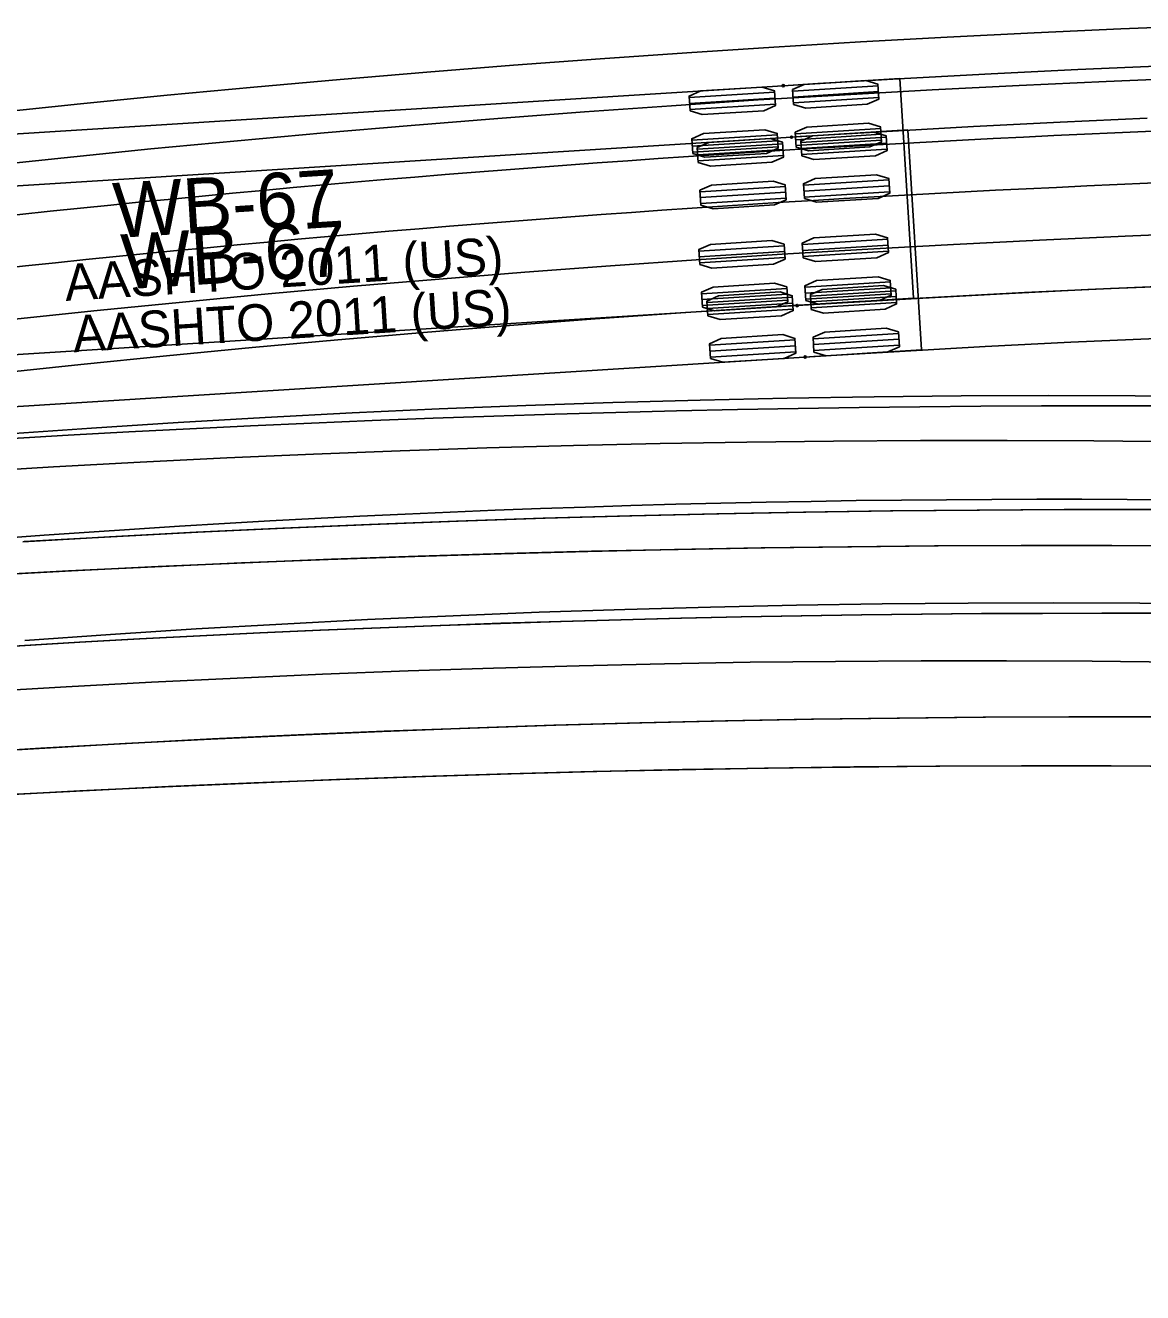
# Model space of a CAD drawing. Extents: x 916040 to 917457, y 328936 to 330267.
# Drawn here: x 916202.02 to 916245.13, y 329686.13 to 329735.02 of the extents above; entities that cross this region are included whole.
import ezdxf

# ---------------------------------------------------------------- set-up
doc = ezdxf.new("R2010")
doc.units = 0
for name, color, linetype in [('EB_LeftontoManchester_WB67', 7, 'Continuous'), ('EB_LeftontoManchester_WB67_v2', 7, 'Continuous'), ('EB_RightontoSaco_WB67_v2', 7, 'Continuous'), ('EB_Thru_WB67', 7, 'Continuous'), ('EB_Thru_WB67_v2', 7, 'Continuous'), ('SB_RightontoRoute25_WB67_v2', 7, 'Continuous'), ('WB_Thru_WB67', 7, 'Continuous')]:
    doc.layers.add(name, color=color, linetype=linetype)

msp = doc.modelspace()

# ---------------------------------------------------------------- linework, layer by layer
at = {"layer": 'EB_LeftontoManchester_WB67'}
for points in [[(916201.221, 329719.252), (916204.57, 329719.487), (916207.921, 329719.702), (916211.273, 329719.897), (916214.627, 329720.072), (916217.982, 329720.226), (916221.338, 329720.36), (916224.695, 329720.474), (916228.053, 329720.567), (916231.412, 329720.64), (916234.77, 329720.692), (916238.129, 329720.725), (916241.489, 329720.736), (916244.848, 329720.728), (916248.207, 329720.699)], [(916199.764, 329717.786), (916203.105, 329717.985), (916206.447, 329718.167), (916209.79, 329718.332), (916213.133, 329718.479), (916216.478, 329718.609), (916219.823, 329718.72), (916223.169, 329718.814), (916226.515, 329718.889), (916229.862, 329718.946), (916233.209, 329718.984), (916236.556, 329719.004), (916239.903, 329719.005), (916243.251, 329718.987), (916246.598, 329718.95)], [(916201.997, 329711.29), (916205.303, 329711.522), (916208.609, 329711.733), (916211.916, 329711.924), (916215.224, 329712.095), (916218.533, 329712.246), (916221.842, 329712.377), (916225.152, 329712.488), (916228.463, 329712.578), (916231.774, 329712.649), (916235.085, 329712.699), (916238.397, 329712.73), (916241.708, 329712.74), (916245.019, 329712.731), (916248.331, 329712.701)], [(916200.293, 329709.303), (916203.591, 329709.499), (916206.889, 329709.679), (916210.188, 329709.841), (916213.487, 329709.987), (916216.786, 329710.114), (916220.086, 329710.224), (916223.385, 329710.316), (916226.685, 329710.391), (916229.985, 329710.447), (916233.285, 329710.484), (916236.585, 329710.504), (916239.884, 329710.505), (916243.184, 329710.487), (916246.482, 329710.451)]]:
    msp.add_lwpolyline(points, dxfattribs=at)
msp.add_arc((916241.758, 329166.738), 550, 75.00607, 98.25153, dxfattribs=at)
at = {"layer": 'EB_LeftontoManchester_WB67_v2'}
for points in [[(916201.92, 329715.101), (916205.265, 329715.291), (916208.61, 329715.466), (916211.957, 329715.624), (916215.304, 329715.767), (916218.652, 329715.894), (916222, 329716.005), (916225.349, 329716.1), (916228.699, 329716.179), (916232.048, 329716.243), (916235.398, 329716.29), (916238.749, 329716.322), (916242.099, 329716.338), (916245.449, 329716.338)], [(916200.346, 329713.797), (916203.684, 329713.973), (916207.023, 329714.136), (916210.362, 329714.283), (916213.703, 329714.417), (916217.043, 329714.535), (916220.385, 329714.639), (916223.726, 329714.728), (916227.069, 329714.803), (916230.411, 329714.862), (916233.754, 329714.906), (916237.097, 329714.936), (916240.44, 329714.95), (916243.783, 329714.949), (916247.126, 329714.933)], [(916199.251, 329706.924), (916202.558, 329707.127), (916205.866, 329707.314), (916209.175, 329707.486), (916212.484, 329707.642), (916215.794, 329707.782), (916219.104, 329707.907), (916222.415, 329708.016), (916225.727, 329708.109), (916229.039, 329708.187), (916232.351, 329708.249), (916235.663, 329708.295), (916238.976, 329708.326), (916242.289, 329708.341), (916245.601, 329708.34)], [(916200.815, 329705.31), (916204.117, 329705.484), (916207.419, 329705.645), (916210.722, 329705.791), (916214.025, 329705.923), (916217.328, 329706.04), (916220.632, 329706.143), (916223.936, 329706.231), (916227.24, 329706.304), (916230.545, 329706.363), (916233.849, 329706.407), (916237.154, 329706.436), (916240.458, 329706.45), (916243.763, 329706.449), (916247.067, 329706.433)]]:
    msp.add_lwpolyline(points, dxfattribs=at)
msp.add_arc((916243.774, 329008.841), 703.5, 74.309906, 98.540079, dxfattribs=at)
at = {"layer": 'EB_RightontoSaco_WB67_v2'}
for points in [[(916201.221, 329719.252), (916204.57, 329719.487), (916207.921, 329719.702), (916211.273, 329719.897), (916214.627, 329720.072), (916217.982, 329720.226), (916221.338, 329720.36), (916224.695, 329720.474), (916228.053, 329720.567), (916231.412, 329720.64), (916234.77, 329720.692), (916238.129, 329720.725), (916241.489, 329720.736), (916244.848, 329720.728), (916248.207, 329720.699)], [(916199.764, 329717.786), (916203.105, 329717.985), (916206.447, 329718.167), (916209.79, 329718.332), (916213.133, 329718.479), (916216.478, 329718.609), (916219.823, 329718.72), (916223.169, 329718.814), (916226.515, 329718.889), (916229.862, 329718.946), (916233.209, 329718.984), (916236.556, 329719.004), (916239.903, 329719.005), (916243.251, 329718.987), (916246.598, 329718.95)], [(916201.997, 329711.29), (916205.303, 329711.522), (916208.609, 329711.733), (916211.916, 329711.924), (916215.224, 329712.095), (916218.533, 329712.246), (916221.842, 329712.377), (916225.152, 329712.488), (916228.463, 329712.578), (916231.774, 329712.649), (916235.085, 329712.699), (916238.397, 329712.73), (916241.708, 329712.74), (916245.019, 329712.731), (916248.331, 329712.701)], [(916200.293, 329709.303), (916203.591, 329709.499), (916206.889, 329709.679), (916210.188, 329709.841), (916213.487, 329709.987), (916216.786, 329710.114), (916220.086, 329710.224), (916223.385, 329710.316), (916226.685, 329710.391), (916229.985, 329710.447), (916233.285, 329710.484), (916236.585, 329710.504), (916239.884, 329710.505), (916243.184, 329710.487), (916246.482, 329710.451)]]:
    msp.add_lwpolyline(points, dxfattribs=at)
msp.add_arc((916241.758, 329166.738), 550, 75.00607, 98.25153, dxfattribs=at)
at = {"layer": 'EB_Thru_WB67'}
for points in [[(916201.221, 329719.252), (916204.57, 329719.487), (916207.921, 329719.702), (916211.273, 329719.897), (916214.627, 329720.072), (916217.982, 329720.226), (916221.338, 329720.36), (916224.695, 329720.474), (916228.053, 329720.567), (916231.412, 329720.64), (916234.77, 329720.692), (916238.129, 329720.725), (916241.489, 329720.736), (916244.848, 329720.728), (916248.207, 329720.699)], [(916199.764, 329717.786), (916203.105, 329717.985), (916206.447, 329718.167), (916209.79, 329718.332), (916213.133, 329718.479), (916216.478, 329718.609), (916219.823, 329718.72), (916223.169, 329718.814), (916226.515, 329718.889), (916229.862, 329718.946), (916233.209, 329718.984), (916236.556, 329719.004), (916239.903, 329719.005), (916243.251, 329718.987), (916246.598, 329718.95)], [(916201.997, 329711.29), (916205.303, 329711.522), (916208.609, 329711.733), (916211.916, 329711.924), (916215.224, 329712.095), (916218.533, 329712.246), (916221.842, 329712.377), (916225.152, 329712.488), (916228.463, 329712.578), (916231.774, 329712.649), (916235.085, 329712.699), (916238.397, 329712.73), (916241.708, 329712.74), (916245.019, 329712.731), (916248.331, 329712.701)], [(916200.293, 329709.303), (916203.591, 329709.499), (916206.889, 329709.679), (916210.188, 329709.841), (916213.487, 329709.987), (916216.786, 329710.114), (916220.086, 329710.224), (916223.385, 329710.316), (916226.685, 329710.391), (916229.985, 329710.447), (916233.285, 329710.484), (916236.585, 329710.504), (916239.884, 329710.505), (916243.184, 329710.487), (916246.482, 329710.451)]]:
    msp.add_lwpolyline(points, dxfattribs=at)
for centre, radius, start, end in [((916243.774, 329008.841), 711.5, 74.309906, 98.540079), ((916241.758, 329166.738), 550, 75.00607, 98.25153)]:
    msp.add_arc(centre, radius, start, end, dxfattribs=at)
at = {"layer": 'EB_Thru_WB67_v2'}
for points in [[(916201.978, 329715.104), (916205.325, 329715.294), (916208.674, 329715.469), (916212.023, 329715.627), (916215.374, 329715.77), (916218.725, 329715.896), (916222.076, 329716.007), (916225.428, 329716.102), (916228.78, 329716.181), (916232.133, 329716.244), (916235.486, 329716.291), (916238.84, 329716.323), (916242.193, 329716.338), (916245.546, 329716.338)], [(916200.461, 329713.803), (916203.802, 329713.979), (916207.144, 329714.141), (916210.487, 329714.289), (916213.83, 329714.421), (916217.174, 329714.54), (916220.518, 329714.643), (916223.863, 329714.732), (916227.208, 329714.806), (916230.553, 329714.864), (916233.899, 329714.908), (916237.245, 329714.937), (916240.591, 329714.95), (916243.937, 329714.949), (916247.283, 329714.932)], [(916199.305, 329706.927), (916202.615, 329707.13), (916205.926, 329707.318), (916209.238, 329707.489), (916212.55, 329707.645), (916215.863, 329707.785), (916219.176, 329707.91), (916222.49, 329708.018), (916225.805, 329708.111), (916229.12, 329708.189), (916232.435, 329708.25), (916235.75, 329708.296), (916239.066, 329708.326), (916242.382, 329708.341), (916245.697, 329708.34)], [(916200.929, 329705.316), (916204.233, 329705.49), (916207.539, 329705.65), (916210.844, 329705.796), (916214.151, 329705.927), (916217.457, 329706.044), (916220.764, 329706.147), (916224.071, 329706.234), (916227.378, 329706.307), (916230.686, 329706.365), (916233.993, 329706.409), (916237.301, 329706.437), (916240.608, 329706.45), (916243.916, 329706.449), (916247.223, 329706.432)]]:
    msp.add_lwpolyline(points, dxfattribs=at)
msp.add_arc((916243.774, 329008.841), 703.5, 74.315114, 98.540079, dxfattribs=at)
at = {"layer": 'SB_RightontoRoute25_WB67_v2'}
for p, q in [((916236.071, 329730.99), (916183.175, 329727.673)), ((916231.943, 329730.501), (916235.237, 329730.708)), ((916236.603, 329722.506), (916236.071, 329730.99)), ((916227.951, 329730.251), (916231.245, 329730.457)), ((916227.966, 329730.022), (916231.259, 329730.229)), ((916231.958, 329730.272), (916235.251, 329730.479)), ((916231.972, 329730.044), (916235.266, 329730.25)), ((916227.98, 329729.793), (916231.273, 329730)), ((916228.054, 329728.604), (916231.348, 329728.811)), ((916232.047, 329728.854), (916235.34, 329729.061)), ((916232.061, 329728.626), (916235.355, 329728.832)), ((916228.069, 329728.375), (916231.362, 329728.582)), ((916228.083, 329728.147), (916231.377, 329728.353)), ((916232.075, 329728.397), (916235.369, 329728.603)), ((916228.323, 329724.329), (916231.616, 329724.536)), ((916232.315, 329724.579), (916235.608, 329724.786)), ((916232.329, 329724.351), (916235.623, 329724.557)), ((916232.343, 329724.122), (916235.637, 329724.329)), ((916228.337, 329724.1), (916231.63, 329724.307)), ((916228.351, 329723.872), (916231.645, 329724.078)), ((916228.426, 329722.682), (916231.719, 329722.889)), ((916232.418, 329722.933), (916235.711, 329723.139)), ((916232.432, 329722.704), (916235.726, 329722.91)), ((916183.707, 329719.19), (916236.603, 329722.506)), ((916228.44, 329722.454), (916231.734, 329722.66)), ((916228.454, 329722.225), (916231.748, 329722.431)), ((916232.447, 329722.475), (916235.74, 329722.682))]:
    msp.add_line(p, q, dxfattribs=at)
for points in [[(916247.074, 329733), (916243.718, 329732.861), (916240.363, 329732.707), (916237.008, 329732.535), (916233.654, 329732.348), (916230.302, 329732.143), (916226.95, 329731.923), (916223.599, 329731.685), (916220.25, 329731.432), (916216.902, 329731.161), (916213.555, 329730.875), (916210.21, 329730.572), (916206.866, 329730.252), (916203.524, 329729.916), (916200.183, 329729.564)], [(916245.3, 329731.436), (916241.952, 329731.283), (916238.605, 329731.114), (916235.259, 329730.93), (916231.914, 329730.729), (916231.58, 329730.708)], [(916247.207, 329725.001), (916243.891, 329724.864), (916240.574, 329724.71), (916237.259, 329724.54), (916233.944, 329724.353), (916230.631, 329724.151), (916227.318, 329723.932), (916224.007, 329723.696), (916220.697, 329723.445), (916217.388, 329723.177), (916214.08, 329722.893), (916210.774, 329722.592), (916207.47, 329722.276), (916204.167, 329721.943), (916200.865, 329721.594)], [(916245.665, 329722.943), (916242.358, 329722.793), (916239.052, 329722.626), (916235.746, 329722.444), (916232.442, 329722.245), (916232.112, 329722.225)]]:
    msp.add_lwpolyline(points, dxfattribs=at)
for points in [[(916231.976, 329729.987), (916231.94, 329730.558), (916232.39, 329730.759), (916234.761, 329730.907), (916235.233, 329730.764), (916235.269, 329730.193), (916234.819, 329729.993), (916232.448, 329729.844)], [(916227.983, 329729.737), (916227.948, 329730.308), (916228.398, 329730.508), (916230.769, 329730.657), (916231.241, 329730.514), (916231.277, 329729.943), (916230.827, 329729.742), (916228.455, 329729.594)], [(916232.079, 329728.34), (916232.043, 329728.911), (916232.493, 329729.112), (916234.865, 329729.261), (916235.337, 329729.118), (916235.372, 329728.547), (916234.922, 329728.346), (916232.551, 329728.197)], [(916228.087, 329728.09), (916228.051, 329728.661), (916228.501, 329728.862), (916230.873, 329729.01), (916231.344, 329728.867), (916231.38, 329728.296), (916230.93, 329728.096), (916228.559, 329727.947)], [(916232.347, 329724.065), (916232.311, 329724.636), (916232.761, 329724.837), (916235.133, 329724.986), (916235.605, 329724.843), (916235.64, 329724.272), (916235.19, 329724.071), (916232.819, 329723.922)], [(916228.355, 329723.815), (916228.319, 329724.386), (916228.769, 329724.587), (916231.141, 329724.735), (916231.612, 329724.592), (916231.648, 329724.021), (916231.198, 329723.821), (916228.827, 329723.672)], [(916232.45, 329722.419), (916232.414, 329722.989), (916232.865, 329723.19), (916235.236, 329723.339), (916235.708, 329723.196), (916235.744, 329722.625), (916235.293, 329722.424), (916232.922, 329722.275)], [(916228.458, 329722.168), (916228.422, 329722.739), (916228.873, 329722.94), (916231.244, 329723.089), (916231.716, 329722.946), (916231.752, 329722.375), (916231.301, 329722.174), (916228.93, 329722.025)]]:
    msp.add_lwpolyline(points, close=True, dxfattribs=at)
for centre in [(916231.58, 329730.708), (916232.112, 329722.225)]:
    msp.add_circle(centre, 0.0417, dxfattribs=at)
msp.add_arc((916273.509, 329050.513), 679, 86.336243, 99.016626, dxfattribs=at)
msp.add_arc((916273.509, 329050.513), 679, 86.336243, 99.016626, dxfattribs=at)
msp.add_arc((916273.509, 329050.513), 679, 86.336243, 99.016626, dxfattribs=at)
at = {"layer": 'WB_Thru_WB67'}
for p, q in [((916235.756, 329732.976), (916182.86, 329729.649)), ((916231.628, 329732.487), (916234.922, 329732.694)), ((916236.289, 329724.493), (916235.756, 329732.976)), ((916227.636, 329732.236), (916230.93, 329732.443)), ((916227.651, 329732.007), (916230.944, 329732.215)), ((916231.643, 329732.258), (916234.936, 329732.466)), ((916231.657, 329732.03), (916234.951, 329732.237)), ((916227.665, 329731.779), (916230.959, 329731.986)), ((916227.74, 329730.589), (916231.033, 329730.796)), ((916231.732, 329730.84), (916235.025, 329731.048)), ((916231.746, 329730.612), (916235.04, 329730.819)), ((916227.754, 329730.361), (916231.048, 329730.568)), ((916227.769, 329730.132), (916231.062, 329730.339)), ((916231.761, 329730.383), (916235.054, 329730.59)), ((916232.001, 329726.566), (916235.294, 329726.773)), ((916228.009, 329726.314), (916231.302, 329726.522)), ((916228.023, 329726.086), (916231.317, 329726.293)), ((916232.015, 329726.337), (916235.309, 329726.544)), ((916232.03, 329726.108), (916235.323, 329726.315)), ((916228.037, 329725.857), (916231.331, 329726.064)), ((916228.112, 329724.668), (916231.406, 329724.875)), ((916232.104, 329724.919), (916235.398, 329725.126)), ((916232.119, 329724.69), (916235.412, 329724.897)), ((916183.394, 329721.166), (916236.289, 329724.493)), ((916228.127, 329724.439), (916231.42, 329724.646)), ((916228.141, 329724.21), (916231.435, 329724.417)), ((916232.133, 329724.461), (916235.427, 329724.669))]:
    msp.add_line(p, q, dxfattribs=at)
for points in [[(916247.643, 329735.023), (916244.292, 329734.888), (916240.941, 329734.737), (916237.591, 329734.569), (916234.243, 329734.385), (916230.895, 329734.184), (916227.548, 329733.968), (916224.202, 329733.734), (916220.857, 329733.485), (916217.514, 329733.219), (916214.172, 329732.936), (916210.831, 329732.638), (916207.492, 329732.323), (916204.154, 329731.991), (916200.819, 329731.644)], [(916245.967, 329733.467), (916242.624, 329733.318), (916239.282, 329733.154), (916235.941, 329732.973), (916232.601, 329732.777), (916231.265, 329732.694)], [(916247.769, 329727.024), (916244.457, 329726.89), (916241.145, 329726.74), (916237.835, 329726.573), (916234.525, 329726.391), (916231.216, 329726.192), (916227.908, 329725.976), (916224.601, 329725.745), (916221.296, 329725.497), (916217.991, 329725.234), (916214.688, 329724.954), (916211.387, 329724.658), (916208.087, 329724.345), (916204.788, 329724.017), (916201.491, 329723.672)], [(916246.322, 329724.974), (916243.02, 329724.827), (916239.718, 329724.665), (916236.418, 329724.487), (916233.118, 329724.293), (916231.798, 329724.211)]]:
    msp.add_lwpolyline(points, dxfattribs=at)
for points in [[(916227.669, 329731.722), (916227.633, 329732.293), (916228.083, 329732.494), (916230.454, 329732.643), (916230.926, 329732.5), (916230.962, 329731.929), (916230.512, 329731.728), (916228.141, 329731.579)], [(916231.661, 329731.973), (916231.625, 329732.544), (916232.075, 329732.745), (916234.446, 329732.894), (916234.918, 329732.751), (916234.954, 329732.18), (916234.504, 329731.979), (916232.133, 329731.83)], [(916231.764, 329730.326), (916231.728, 329730.897), (916232.179, 329731.098), (916234.55, 329731.247), (916235.022, 329731.104), (916235.058, 329730.533), (916234.608, 329730.332), (916232.236, 329730.183)], [(916227.772, 329730.075), (916227.736, 329730.646), (916228.187, 329730.847), (916230.558, 329730.996), (916231.03, 329730.853), (916231.066, 329730.282), (916230.615, 329730.081), (916228.244, 329729.932)], [(916232.033, 329726.051), (916231.997, 329726.622), (916232.448, 329726.823), (916234.819, 329726.972), (916235.291, 329726.829), (916235.327, 329726.259), (916234.876, 329726.058), (916232.505, 329725.908)], [(916228.041, 329725.8), (916228.005, 329726.371), (916228.455, 329726.572), (916230.827, 329726.721), (916231.299, 329726.578), (916231.335, 329726.007), (916230.884, 329725.806), (916228.513, 329725.657)], [(916232.137, 329724.405), (916232.101, 329724.976), (916232.551, 329725.177), (916234.922, 329725.326), (916235.394, 329725.183), (916235.43, 329724.612), (916234.98, 329724.411), (916232.609, 329724.262)], [(916228.145, 329724.154), (916228.109, 329724.724), (916228.559, 329724.925), (916230.93, 329725.075), (916231.402, 329724.932), (916231.438, 329724.361), (916230.988, 329724.16), (916228.617, 329724.011)]]:
    msp.add_lwpolyline(points, close=True, dxfattribs=at)
for centre in [(916231.265, 329732.694), (916231.798, 329724.211)]:
    msp.add_circle(centre, 0.0417, dxfattribs=at)
msp.add_arc((916273.509, 329050.513), 681, 86.336243, 99.016626, dxfattribs=at)

# ---------------------------------------------------------------- texts
at = {"layer": 'SB_RightontoRoute25_WB67_v2'}
for s, height, p in [('WB-67', 2.125, (916205.799, 329724.833)), ('AASHTO 2011 (US)', 1.41667, (916203.893, 329722.407))]:
    msp.add_text(s, height=height, rotation=3.5876, dxfattribs=at).set_placement(p)
at = {"layer": 'WB_Thru_WB67'}
for s, height, p in [('WB-67', 2.125, (916205.485, 329726.814)), ('AASHTO 2011 (US)', 1.41667, (916203.579, 329724.388))]:
    msp.add_text(s, height=height, rotation=3.5991, dxfattribs=at).set_placement(p)

doc.saveas('drawing.dxf')
